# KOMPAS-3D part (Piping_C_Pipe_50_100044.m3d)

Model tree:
1. Plane XY
2. Plane ZX
3. Plane ZY
4. X Axis
5. Y Axis
6. Z Axis
7. Origin
8. Path  (labels: Тройник Dy 50; Труба Dy 50; Отвод 90 Dy 50)
9. Plane of section
10. Section of pipe
11. Pipe
     Толщина стенки 1 = 1

Referenced files in C:\Program Files\ASCON\KOMPAS-3D V10\Libs\Piping\Models\Tanks\: Tanks.a3d
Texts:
  Pipe Dn 50
  Three Point Plane
  Plane at Angle
  Line and Point Plane
  Axis through Two Vertices
  Axis of Feature
  Axis of Conical Surface
  Axis through Edge
  Приклеить элемент выдавливания
  Приклеить элемент вращения
  Приклеить кинематический элемент
  Приклеить элемент по сечениям
  Trim by Surface
  Trim by Sketch
  Feature with No History
  Intersection Axis of Two Planes
  Two Line Plane
  Line and Face Plane
  Bend by line
  Hole in sheet body
  Cut in sheet body
  Point in CM
  Linear Dimension from Line to Point
  Surface Finish Symbol
  Geometric Tolerance Symbol
  Текст на чертеже
  Линия-выноска #1
  Линия-выноска #2
  Линия-выноска #3
  Отклонения формы и база
  Марка координационной оси
  Марка/позиционное обозначение с линией-выноской
  Марка/позиционное обозначение на линии
  Марка/позиционное обозначение без линии-выноски
  Тройник Dy 50
  Труба Dy 50
  Отвод 90 Dy 50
